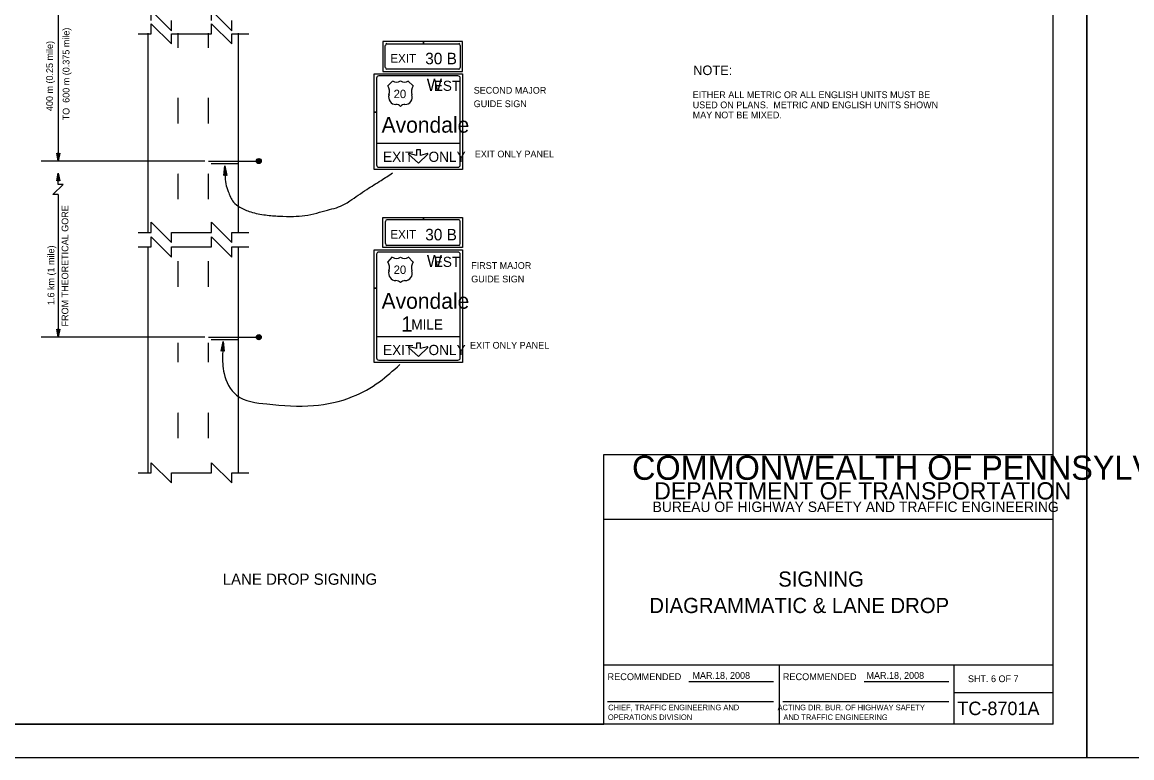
# Model space of a CAD drawing. Extents: x 640994 to 644422, y 298458 to 299646.
# Drawn here: x 642202.5 to 642696.3, y 298457.6 to 298785.1 of the extents above; entities that cross this region are included whole.
import ezdxf

# ---------------------------------------------------------------- set-up
doc = ezdxf.new("R2010")
doc.units = 0
for name, color, linetype in [('1', 7, 'Continuous'), ('2', 7, 'Continuous'), ('PLT-BNDY', 7, 'Continuous'), ('XCS-GRID-MIN', 7, 'Continuous')]:
    doc.layers.add(name, color=color, linetype=linetype)

msp = doc.modelspace()

# ---------------------------------------------------------------- linework, layer by layer
at = {"layer": '1'}
for p, q in [((642661.31, 298472.63), (642661.31, 299036.63)), ((642461.31, 298472.63), (642461.31, 298592.63)), ((642461.31, 298592.63), (642661.31, 298592.63)), ((642661.31, 298563.63), (642461.31, 298563.63)), ((642461.31, 298499), (642661.31, 298499)), ((642539.31, 298499), (642539.31, 298472.63)), ((642617.19, 298472.63), (642617.19, 298499)), ((642499.24, 298491.57), (642536.87, 298491.57)), ((642577.24, 298491.57), (642614.87, 298491.57)), ((642617.19, 298486.63), (642661.31, 298486.63)), ((642462.99, 298482.68), (642536.87, 298482.68)), ((642540.99, 298482.68), (642614.87, 298482.68)), ((642661.31, 298472.63), (641875.31, 298472.63)), ((641875.31, 298472.63), (642461.31, 298472.63))]:
    msp.add_line(p, q, dxfattribs=at)
at = {"layer": '2'}
for p, q in [((642218.56, 298821.75), (642218.56, 298723.25)), ((642254.06, 298779.88), (642259.94, 298779.88)), ((642258.56, 298691.5), (642258.56, 298780.13)), ((642268.94, 298779.88), (642286.81, 298779.88)), ((642271.94, 298773.63), (642271.94, 298780.13)), ((642285.44, 298773.63), (642285.44, 298780.13)), ((642295.81, 298779.88), (642303.31, 298779.88)), ((642298.81, 298691.5), (642298.81, 298780.13)), ((642271.94, 298773.63), (642271.94, 298773.63)), ((642285.44, 298773.63), (642285.44, 298773.63)), ((642381.12, 298776.5), (642363.06, 298776.5)), ((642363.06, 298776.5), (642363.06, 298763.13)), ((642364.06, 298764.88), (642364.06, 298774.75)), ((642364.81, 298775.5), (642381.12, 298775.5)), ((642381.12, 298775.5), (642381.12, 298776.5)), ((642398.44, 298776.5), (642381.12, 298776.5)), ((642381.12, 298776.5), (642381.12, 298775.5)), ((642381.12, 298775.5), (642396.81, 298775.5)), ((642397.44, 298774.75), (642397.44, 298764.88)), ((642398.44, 298763.13), (642398.44, 298776.5)), ((642363.06, 298763.13), (642398.44, 298763.13)), ((642396.81, 298764.13), (642364.81, 298764.13)), ((642359.19, 298745.06), (642359.19, 298762.13)), ((642359.19, 298762.13), (642398.44, 298762.13)), ((642360.19, 298760.13), (642360.19, 298745.06)), ((642396.44, 298761.13), (642361.19, 298761.13)), ((642365.19, 298756.75), (642367.31, 298758.88)), ((642374.31, 298758.88), (642376.56, 298756.75)), ((642397.44, 298721.5), (642397.44, 298760.13)), ((642398.44, 298762.13), (642398.44, 298719.5)), ((642271.94, 298751.38), (642271.94, 298751.38)), ((642271.94, 298740), (642271.94, 298751.38)), ((642285.44, 298751.38), (642285.44, 298751.38)), ((642285.44, 298740), (642285.44, 298751.38)), ((642368.81, 298748.38), (642368.81, 298748.38)), ((642370.81, 298753.13), (642370.81, 298753.13)), ((642370.81, 298753.13), (642370.81, 298753.13)), ((642370.81, 298753.13), (642370.81, 298753.13)), ((642370.81, 298753.13), (642370.81, 298753.13)), ((642370.81, 298753.13), (642370.81, 298753.13)), ((642372.94, 298748.38), (642372.94, 298748.38)), ((642373.06, 298751.13), (642373.06, 298751.13)), ((642376.06, 298751.75), (642376.06, 298751.75)), ((642360.19, 298745.06), (642359.19, 298745.06)), ((642359.19, 298719.5), (642359.19, 298745.06)), ((642359.19, 298745.06), (642360.19, 298745.06)), ((642360.19, 298745.06), (642360.19, 298721.5)), ((642271.94, 298740), (642271.94, 298740)), ((642285.44, 298740), (642285.44, 298740)), ((642378.69, 298739.38), (642378.69, 298739.38)), ((642218.56, 298723.25), (642217.94, 298726.75)), ((642217.94, 298726.75), (642218.19, 298726.63)), ((642218.44, 298726.5), (642218.19, 298726.63)), ((642218.19, 298726.63), (642218.56, 298723.25)), ((642218.56, 298723.25), (642218.44, 298726.5)), ((642219.19, 298726.75), (642218.56, 298723.25)), ((642218.56, 298723.25), (642219.06, 298726.63)), ((642218.81, 298726.5), (642218.56, 298723.25)), ((642219.06, 298726.63), (642218.81, 298726.5)), ((642219.06, 298726.63), (642219.19, 298726.75)), ((642306.81, 298723.13), (642307.94, 298724.25)), ((642308.56, 298723.75), (642306.81, 298723.13)), ((642307.94, 298724.25), (642306.94, 298723.75)), ((642307.06, 298722.63), (642307.06, 298723.75)), ((642307.06, 298723.75), (642307.44, 298722.5)), ((642307.44, 298722.5), (642307.56, 298724)), ((642307.56, 298724), (642307.94, 298722.38)), ((642307.69, 298722.38), (642308.56, 298723.75)), ((642307.94, 298722.38), (642307.94, 298724.25)), ((642307.94, 298724.25), (642308.31, 298722.5)), ((642308.31, 298722.5), (642308.31, 298724)), ((642308.31, 298724), (642308.56, 298723.13)), ((642374.44, 298726.25), (642378.81, 298722.25)), ((642377.94, 298725.75), (642374.69, 298726.63)), ((642379.69, 298728.25), (642377.94, 298728.25)), ((642378.81, 298722.25), (642383.06, 298726.25)), ((642382.81, 298726.63), (642379.69, 298725.75)), ((642283.81, 298723.25), (642210.94, 298723.25)), ((642285.44, 298723.25), (642307.81, 298723.25)), ((642286.56, 298722.13), (642298.81, 298722.13)), ((642308.56, 298723.13), (642307.69, 298722.38)), ((642307.81, 298723.25), (642307.81, 298723.25)), ((642398.44, 298719.5), (642359.19, 298719.5)), ((642361.19, 298720.5), (642396.44, 298720.5)), ((642217.94, 298714.42), (642218.57, 298717.92)), ((642218.07, 298714.54), (642217.94, 298714.42)), ((642218.57, 298717.92), (642218.07, 298714.54)), ((642218.07, 298714.54), (642218.32, 298714.67)), ((642218.32, 298714.67), (642218.57, 298717.92)), ((642218.57, 298717.92), (642218.69, 298714.67)), ((642218.94, 298714.54), (642218.57, 298717.92)), ((642218.57, 298717.92), (642219.19, 298714.42)), ((642218.69, 298714.67), (642218.94, 298714.54)), ((642219.19, 298714.42), (642218.94, 298714.54)), ((642271.94, 298717.75), (642271.94, 298717.75)), ((642271.94, 298717.63), (642271.94, 298717.63)), ((642271.94, 298706.25), (642271.94, 298717.63)), ((642285.44, 298717.75), (642285.44, 298717.75)), ((642285.44, 298717.63), (642285.44, 298717.63)), ((642285.44, 298706.25), (642285.44, 298717.63)), ((642218.56, 298708.38), (642218.56, 298644.88)), ((642271.94, 298706.38), (642271.94, 298706.38)), ((642271.94, 298706.25), (642271.94, 298706.25)), ((642285.44, 298706.38), (642285.44, 298706.38)), ((642285.44, 298706.25), (642285.44, 298706.25)), ((642363.06, 298684.75), (642363.06, 298698.13)), ((642363.06, 298698.13), (642381.12, 298698.13)), ((642364.06, 298696.38), (642364.06, 298686.5)), ((642381.12, 298697.13), (642364.81, 298697.13)), ((642381.12, 298698.13), (642381.12, 298697.13)), ((642381.12, 298697.13), (642381.12, 298698.13)), ((642381.12, 298698.13), (642398.44, 298698.13)), ((642396.81, 298697.13), (642381.12, 298697.13)), ((642397.44, 298686.5), (642397.44, 298696.38)), ((642398.44, 298698.13), (642398.44, 298684.75)), ((642254.06, 298691.5), (642259.94, 298691.5)), ((642268.94, 298691.5), (642286.81, 298691.5)), ((642295.81, 298691.5), (642303.31, 298691.5)), ((642254.06, 298685), (642259.94, 298685)), ((642258.56, 298584.25), (642258.56, 298685)), ((642268.94, 298685), (642286.81, 298685)), ((642295.81, 298685), (642303.31, 298685)), ((642298.81, 298584.25), (642298.81, 298685)), ((642398.44, 298684.75), (642363.06, 298684.75)), ((642364.81, 298685.75), (642396.81, 298685.75)), ((642359.19, 298683.75), (642398.44, 298683.75)), ((642396.44, 298682.75), (642361.19, 298682.75)), ((642365.19, 298678.25), (642367.31, 298680.63)), ((642374.31, 298680.63), (642376.56, 298678.25)), ((642397.44, 298635.63), (642397.44, 298681.75)), ((642398.44, 298683.75), (642398.44, 298633.63)), ((642271.94, 298678.63), (642271.94, 298678.63)), ((642271.94, 298667.25), (642271.94, 298678.63)), ((642285.44, 298678.63), (642285.44, 298678.63)), ((642285.44, 298667.25), (642285.44, 298678.63)), ((642370.81, 298674.88), (642370.81, 298674.88)), ((642370.81, 298674.88), (642370.81, 298674.88)), ((642370.81, 298674.88), (642370.81, 298674.88)), ((642370.81, 298674.88), (642370.81, 298674.88)), ((642368.81, 298670), (642368.81, 298670)), ((642372.94, 298670), (642372.94, 298670)), ((642373.06, 298672.63), (642373.06, 298672.63)), ((642376.06, 298673.25), (642376.06, 298673.25)), ((642271.94, 298667.25), (642271.94, 298667.25)), ((642285.44, 298667.25), (642285.44, 298667.25)), ((642360.19, 298666.65), (642359.19, 298666.65)), ((642359.19, 298666.65), (642360.19, 298666.65)), ((642283.81, 298644.88), (642210.94, 298644.88)), ((642218.56, 298644.88), (642217.94, 298648.38)), ((642217.94, 298648.38), (642218.19, 298648.25)), ((642218.44, 298648.13), (642218.19, 298648.25)), ((642218.19, 298648.25), (642218.56, 298644.88)), ((642218.56, 298644.88), (642218.44, 298648.13)), ((642219.19, 298648.38), (642218.56, 298644.88)), ((642218.56, 298644.88), (642219.06, 298648.25)), ((642218.81, 298648.13), (642218.56, 298644.88)), ((642219.06, 298648.25), (642218.81, 298648.13)), ((642219.06, 298648.25), (642219.19, 298648.38)), ((642271.94, 298645), (642271.94, 298645)), ((642285.44, 298645), (642285.44, 298645)), ((642285.44, 298644.88), (642307.81, 298644.88)), ((642306.81, 298644.63), (642307.94, 298645.75)), ((642308.56, 298645.38), (642306.81, 298644.63)), ((642307.94, 298645.75), (642306.94, 298645.5)), ((642307.06, 298644.25), (642307.06, 298645.25)), ((642307.06, 298645.25), (642307.44, 298644)), ((642307.44, 298644), (642307.56, 298645.63)), ((642307.56, 298645.63), (642307.94, 298643.88)), ((642307.69, 298643.88), (642308.56, 298645.38)), ((642308.56, 298644.75), (642307.69, 298643.88)), ((642307.81, 298644.88), (642307.81, 298644.88)), ((642307.94, 298643.88), (642307.94, 298645.75)), ((642307.94, 298645.75), (642308.31, 298644.13)), ((642308.31, 298644.13), (642308.31, 298645.63)), ((642308.31, 298645.63), (642308.56, 298644.75)), ((642360.19, 298645.13), (642397.44, 298645.13)), ((642271.94, 298633.75), (642271.94, 298642.38)), ((642285.44, 298633.75), (642285.44, 298642.38)), ((642286.56, 298643.75), (642298.81, 298643.75)), ((642374.44, 298640.25), (642378.81, 298636.25)), ((642377.94, 298639.75), (642374.69, 298640.63)), ((642379.69, 298642.25), (642377.94, 298642.25)), ((642378.81, 298636.25), (642383.06, 298640.25)), ((642382.81, 298640.63), (642379.69, 298639.75)), ((642271.94, 298633.75), (642271.94, 298633.75)), ((642285.44, 298633.75), (642285.44, 298633.75)), ((642398.44, 298633.63), (642359.19, 298633.63)), ((642361.19, 298634.63), (642396.44, 298634.63)), ((642271.94, 298611.38), (642271.94, 298611.38)), ((642271.94, 298611.25), (642271.94, 298611.25)), ((642271.94, 298599.88), (642271.94, 298611.25)), ((642285.44, 298611.38), (642285.44, 298611.38)), ((642285.44, 298611.25), (642285.44, 298611.25)), ((642285.44, 298599.88), (642285.44, 298611.25)), ((642271.94, 298600), (642271.94, 298600)), ((642271.94, 298599.88), (642271.94, 298599.88)), ((642285.44, 298600), (642285.44, 298600)), ((642285.44, 298599.88), (642285.44, 298599.88)), ((642254.06, 298584.5), (642259.94, 298584.5)), ((642258.56, 298584.25), (642258.56, 298584.25)), ((642268.94, 298584.5), (642286.81, 298584.5)), ((642295.81, 298584.5), (642303.31, 298584.5))]:
    msp.add_line(p, q, dxfattribs=at)
for points in [[(642259.94, 298785.75), (642259.94, 298790.25), (642268.94, 298781.25), (642268.94, 298785.75)], [(642286.81, 298785.75), (642286.81, 298790.25), (642295.81, 298781.25), (642295.81, 298785.75)], [(642259.94, 298779.88), (642259.94, 298784.38), (642268.94, 298775.38), (642268.94, 298779.88)], [(642286.81, 298779.88), (642286.81, 298784.38), (642295.81, 298775.38), (642295.81, 298779.88)], [(642360.19, 298731.25), (642397.44, 298731.25)], [(642377.94, 298728.25), (642377.94, 298725.75)], [(642379.69, 298725.75), (642379.69, 298728.25)], [(642292.31, 298717), (642292.56, 298717.13), (642292.69, 298721.13), (642292.31, 298717), (642292.19, 298716.88), (642292.69, 298721.13), (642292.94, 298717.13), (642293.31, 298717), (642292.69, 298721.13), (642293.56, 298716.88), (642293.31, 298717)], [(642218.57, 298708.38), (642216.19, 298708.38), (642220.69, 298712.88), (642218.57, 298712.88), (642218.57, 298717.92)], [(642259.94, 298691.5), (642259.94, 298696), (642268.94, 298687), (642268.94, 298691.5)], [(642286.81, 298691.5), (642286.81, 298696), (642295.81, 298687), (642295.81, 298691.5)], [(642259.94, 298685), (642259.94, 298689.5), (642268.94, 298680.5), (642268.94, 298685)], [(642286.81, 298685), (642286.81, 298689.5), (642295.81, 298680.5), (642295.81, 298685)], [(642359.19, 298666.65), (642359.19, 298683.75)], [(642360.19, 298681.75), (642360.19, 298666.65)], [(642359.19, 298633.63), (642359.19, 298666.65)], [(642360.19, 298666.65), (642360.19, 298635.63)], [(642291.19, 298638.75), (642291.56, 298638.88), (642291.94, 298642.88), (642291.19, 298638.75), (642291.06, 298638.63), (642291.94, 298642.88), (642291.94, 298638.88), (642292.31, 298638.75), (642291.94, 298642.88), (642292.44, 298638.63), (642292.31, 298638.75)], [(642377.94, 298642.25), (642377.94, 298639.75)], [(642379.69, 298639.75), (642379.69, 298642.25)], [(642259.94, 298584.5), (642259.94, 298589), (642268.94, 298580), (642268.94, 298584.5)], [(642286.81, 298584.5), (642286.81, 298589), (642295.81, 298580), (642295.81, 298584.5)]]:
    msp.add_lwpolyline(points, dxfattribs=at)
for centre in [(642307.75, 298723.24), (642307.75, 298644.86)]:
    msp.add_circle(centre, 1.12, dxfattribs=at)
for centre, radius, start, end in [((642361.19, 298760.13), 1, 90, 180), ((642369.08, 298761.24), 2.93, 233.136, 306.864), ((642372.59, 298761.24), 2.93, 233.136, 306.864), ((642396.44, 298760.13), 1, 0, 90), ((642361.41, 298754.14), 4.55, 341.8289, 34.5747), ((642380.25, 298754.14), 4.55, 145.4253, 198.1711), ((642368.83, 298751.69), 3.26, 161.452, 269.9953), ((642368.82, 298745.67), 2.76, 43.7275, 90), ((642372.84, 298745.67), 2.76, 90, 136.2725), ((642372.84, 298751.69), 3.26, 270.0047, 18.548), ((642374.66, 298726.4), 0.217, 75.9638, 226.9667), ((642382.88, 298726.4), 0.217, 313.0251, 104.0537), ((642361.19, 298721.5), 1, 180, 270), ((642396.44, 298721.5), 1, 270, 0), ((642361.19, 298681.75), 1, 90, 180), ((642369.08, 298682.86), 2.93, 233.136, 306.864), ((642372.59, 298682.86), 2.93, 233.136, 306.864), ((642396.44, 298681.75), 1, 0, 90), ((642361.41, 298675.76), 4.55, 341.8289, 34.5747), ((642368.83, 298673.3), 3.26, 161.452, 269.9953), ((642372.84, 298673.3), 3.26, 270.0047, 18.548), ((642380.25, 298675.76), 4.55, 145.4253, 198.1711), ((642368.82, 298667.28), 2.76, 43.7275, 90), ((642372.84, 298667.28), 2.76, 90, 136.2725), ((642374.66, 298640.4), 0.217, 75.9638, 226.9667), ((642382.88, 298640.4), 0.217, 313.0251, 104.0537), ((642361.19, 298635.63), 1, 180, 270), ((642396.44, 298635.63), 1, 270, 0)]:
    msp.add_arc(centre, radius, start, end, dxfattribs=at)
for centre, major_axis, start_param, end_param in [((642364.77, 298774.74), (0, -0.792), 3.141593, 4.712389), ((642396.8, 298774.74), (0, 0.792), 4.712389, 6.283185), ((642364.77, 298764.89), (0, -0.792), 4.712389, 6.283185), ((642396.8, 298764.89), (0, 0.792), 3.141593, 4.712389), ((642364.77, 298696.36), (0, -0.792), 3.141593, 4.712389), ((642396.8, 298696.36), (0, 0.792), 4.712389, 6.283185), ((642364.77, 298686.51), (0, -0.792), 4.712389, 6.283185), ((642396.8, 298686.51), (0, 0.792), 3.141593, 4.712389)]:
    msp.add_ellipse(centre, major_axis=major_axis, ratio=0.827467, start_param=start_param, end_param=end_param, dxfattribs=at)
for points in [[(642292.69, 298721.13), (642292.81, 298717), (642293.06, 298713.13), (642294.19, 298709.75), (642296.56, 298705), (642299.31, 298702.75), (642304.19, 298700.63), (642310.81, 298699.25), (642316.94, 298698.75), (642323.19, 298698.63), (642328.31, 298699), (642333.69, 298700.13), (642338.31, 298701.38), (642342.31, 298702.5), (642345.94, 298704), (642348.31, 298705.5), (642355.81, 298710.63), (642362.19, 298714.63), (642367.31, 298718)], [(642291.94, 298642.88), (642291.69, 298637.13), (642292.31, 298628.75), (642297.94, 298619), (642311.44, 298615.13), (642332.19, 298614.38), (642349.56, 298618.38), (642361.44, 298625), (642370.56, 298632.63)]]:
    msp.add_spline(points, degree=3, dxfattribs=at)
at = {"layer": 'XCS-GRID-MIN'}
for points in [[(641835.31, 299051.63), (642676.31, 299051.63), (642676.31, 298457.63), (641835.31, 298457.63)], [(642676.31, 299051.63), (643517.31, 299051.63), (643517.31, 298457.63), (642676.31, 298457.63)]]:
    msp.add_lwpolyline(points, close=True, dxfattribs=at)

# ---------------------------------------------------------------- texts
at = {"layer": '1'}
for s, height, p in [('COMMONWEALTH OF PENNSYLVANIA', 10.7828, (642473.9, 298581.36)), ('DEPARTMENT OF TRANSPORTATION', 7.6837, (642483.76, 298572.61)), ('BUREAU OF HIGHWAY SAFETY AND TRAFFIC ENGINEERING', 4.6253, (642483.04, 298567.04)), ('SIGNING', 6.75, (642538.96, 298533.81)), ('DIAGRAMMATIC & LANE DROP', 6.75, (642481.59, 298522.06)), ('RECOMMENDED', 3.048, (642462.99, 298492.2)), ('RECOMMENDED', 3.048, (642540.99, 298492.2)), ('SHT. 6 OF 7', 3, (642623.4, 298491.31)), ('TC-8701A', 6, (642618.68, 298476.63))]:
    msp.add_text(s, height=height, dxfattribs=at).set_placement(p)
at = {"layer": '2'}
for s, p in [('TO  600 m (0.375 mile)', (642223.54, 298741.38)), ('  400 m (0.25 mile) ', (642216.18, 298743.26)), ('FROM THEORETICAL GORE', (642223.04, 298649.64)), ('1.6 km (1 mile) ', (642216.8, 298659.16))]:
    msp.add_text(s, height=3, rotation=90, dxfattribs=at).set_placement(p)
for s, height, p in [('EXIT', 3.875, (642366.3, 298767.04)), ('30 B', 5.125, (642381.86, 298766.33)), ('NOTE:', 4.25, (642501.12, 298761.53)), ('W', 5.38, (642382.56, 298754.5)), ('EST', 4.5, (642385.69, 298754.5)), ('20', 3.75, (642367.81, 298751.25)), ('SECOND MAJOR', 3, (642403.44, 298753.25)), ('EITHER ALL METRIC OR ALL ENGLISH UNITS MUST BE', 3, (642500.9, 298751.26)), ('GUIDE SIGN', 3, (642403.44, 298747.25)), ('USED ON PLANS.  METRIC AND ENGLISH UNITS SHOWN', 3, (642500.9, 298746.76)), ('MAY NOT BE MIXED.', 3, (642500.9, 298742.26)), ('Avondale', 7, (642362.44, 298735.88)), ('EXIT    ONLY', 4.5457, (642363.06, 298722.88)), ('EXIT ONLY PANEL', 3, (642403.94, 298724.88)), ('EXIT', 3.875, (642366.3, 298688.67)), ('30 B', 5.125, (642381.86, 298687.95)), ('W', 5.38, (642382.56, 298676.13)), ('EST', 4.5, (642385.69, 298676.13)), ('20', 3.75, (642367.81, 298673)), ('FIRST MAJOR', 3, (642402.31, 298675.25)), ('GUIDE SIGN', 3, (642402.31, 298669.25)), ('Avondale', 7, (642362.44, 298657.5)), ('1', 6.75, (642371.19, 298647.38)), ('MILE', 4.5, (642375.69, 298648.25)), ('EXIT    ONLY', 4.5457, (642363.06, 298636.88)), ('EXIT ONLY PANEL', 3, (642401.81, 298639.75)), ('LANE DROP SIGNING', 5, (642291.71, 298534.65)), ('MAR.18, 2008', 3, (642500.78, 298492.78)), ('MAR.18, 2008', 3, (642578.23, 298492.78))]:
    msp.add_text(s, height=height, dxfattribs=at).set_placement(p)
at = {"layer": 'PLT-BNDY'}
for s, p in [('OPERATIONS DIVISION', (642463.14, 298474.44)), ('CHIEF, TRAFFIC ENGINEERING AND', (642463.28, 298478.81)), ('  ACTING DIR. BUR. OF HIGHWAY SAFETY', (642536.81, 298478.8)), ('  ACTING DIR. BUR. OF HIGHWAY SAFETY', (642536.81, 298478.8))]:
    msp.add_text(s, height=2.5, dxfattribs=at).set_placement(p)
msp.add_text('AND TRAFFIC ENGINEERING', height=2.5, rotation=360, dxfattribs=at).set_placement((642541.25, 298474.43))
msp.add_text('AND TRAFFIC ENGINEERING', height=2.5, rotation=360, dxfattribs=at).set_placement((642541.25, 298474.43))

doc.saveas('drawing.dxf')
